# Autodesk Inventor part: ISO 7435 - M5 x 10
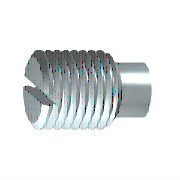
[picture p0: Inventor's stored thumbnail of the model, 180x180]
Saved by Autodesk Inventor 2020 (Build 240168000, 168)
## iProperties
Manager: www.cadconsulting.pl
Company: Fabian Stasiak CAD Consulting
Created: 2015-02
Part Number: ISO 7435 - M5 x 10
Material: Stal nierdzewna 440C
Description: Wkręty dociskowe z rowkiem z długim czopkiem
Document SubType Name: Modeling
Standard: ISO 7435
Designer: F.Stasiak
Standard Revision: First edition 1983-09-01
Standards Organization: ISO
Language: pl-PL
Size Designation: M5 x 10
Categories: <MemberInstance><Categories><Category DisplayName="Mocowania" InternalName="e4da775c-781d-43d5-af7c-5136215cf5a6" Mnemonic="FSTN"><Category DisplayName="Śruby"
Density: 7.75 g/cm^3
Appearance: Częściowo polerowana
IsCustomPart: 0
Author: F.Stasiak
Subject: Zbiór ćwiczeń. Autodesk Inventor 2020. Kurs podstawowy
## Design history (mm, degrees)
sketch "Szkic1"
  geometry: L1 (0, 0)-(10, 0); L2 (10, 0)-(10, 2.5); L3 (10, 2.5)-(2.75, 2.5); L4 (0, -0.5)-(0, 3) reference; L5 (0, 1.75)-(0, 0); L6 (0, 1.75)-(2.75, 1.75); L7 (2.75, 1.75)-(2.75, 2.5)
  constraints: 13 end point, 4 perpendicular, 2 parallel, 1 collinear, 1 point on line
  dimensions: "d1" = 10 distance from line of L2 L5.start (= NLG); "d2" = 3.5 diameter of L5.start L1 (= SPD); "d13" = 5 diameter of L3 L1 (= NND); "d14" = 2.75 distance of L5.start L6.end (= ZLG)
revolve "Bryła" sketch "Szkic1" stored, may be unused: angle "d6" = 90 deg
sketch "Szkic2"
  geometry: L1 (10, 2.009)-(10, -2.009) reference; L2 (8.464, 0)-(10.256, 0) reference; L3 (10, 0.4)-(8.72, 0.4); L4 (8.72, 0.4)-(8.72, 0); L5 (8.72, -0.4)-(8.72, 0); L6 (8.72, -0.4)-(10, -0.4)
  constraints: 8 end point, 3 point on line, 2 perpendicular, 1 parallel, 1 symmetric about line, 1 other
  dimensions: "d8" = 0.4 distance between parallel lines of L2 L3 (= 0.5 x SBR); "d9" = 1.28 distance between parallel lines of L1 L4 (= STI)
extrude "Szczelina" cut sketch "Szkic2" stored distance "d10" = 5 (= NND); taper "d11" = 0 deg
workaxis "Work Axis1"
workplane "Work Plane1"
body "Solid1"
chamfer "Faza1" distance "d3" = 0.49076 (= -0.5 x GD1 + 0.5 x NND); stored, may be unused: angle "d4" = 45 deg (= FAWI), second distance "d37" = 0.49076 (= -0.5 x GD1 + 0.5 x NND)
feature "Gwint" dims "d5" = 7.25 (= NLG - ZLG), "d7" = 0
chamfer "Faza2" distance "d15" = 0.75 (= -0.5 x SPD + 0.5 x NND); stored, may be unused: angle "d16" = 45 deg (= FAWI), second distance "d38" = 0.75 (= -0.5 x SPD + 0.5 x NND)
other parameters: "NND" = 5 [user parameter; used in 6 equation terms], "NLG" = 10 [user parameter; used in 2 equation terms], "FAWI" = 45 deg [user parameter; used in 2 equation terms], "GD1" = 4.01848 (= THREADDIA - 1.2269 x PTC) [user parameter; used in 2 equation terms], "d0" = 0, "FAWI1" = 45 deg [user parameter], "SPD" = 3.5 [user parameter; used in 3 equation terms], "SBR" = 0.8 [user parameter; used in 1 equation term], "STI" = 1.28 [user parameter; used in 1 equation term], "ZLG" = 2.75 [user parameter; used in 2 equation terms], "d17" = 0, "d39" = 90 deg, "d40" = 0, "GUL" = 0.49076 (= 0.61345 x PTC) [user parameter], "TPU" = 12.5 (computed from PTC) [user parameter], "THREADDIA" = 5 [user parameter; used in 1 equation term], "TOA" = 30 deg [user parameter], "PTC" = 0.8 [user parameter; used in 4 equation terms], "GAL" = 0.49076 (= 0.61345 x PTC) [user parameter]
